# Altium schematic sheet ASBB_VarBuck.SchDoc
size A4
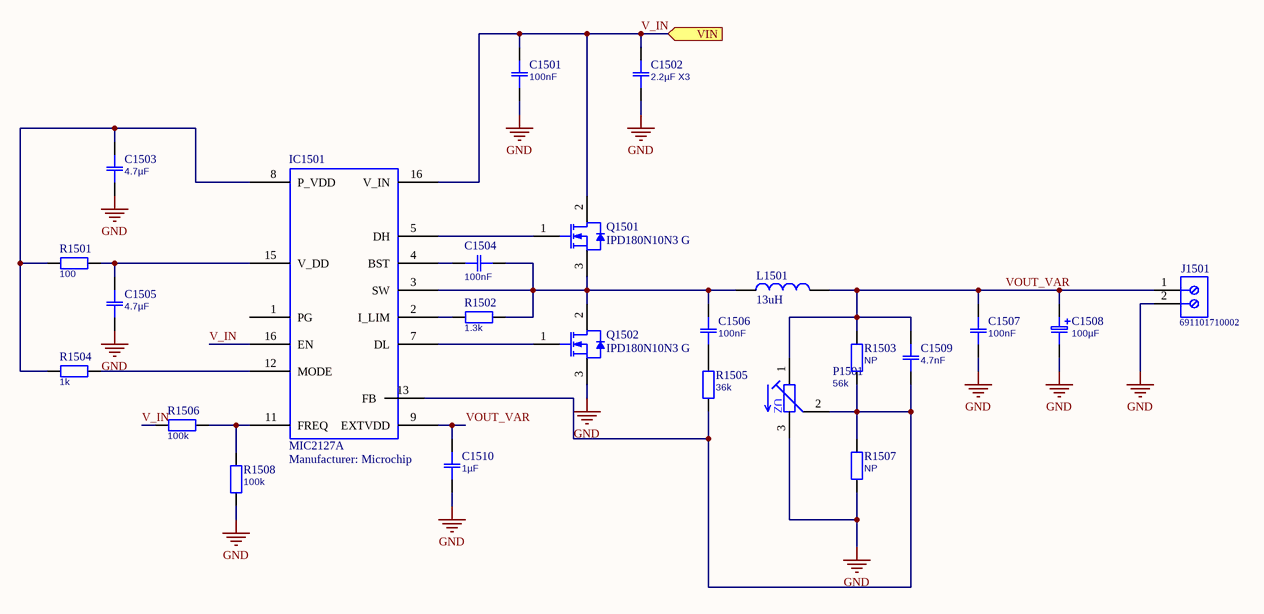
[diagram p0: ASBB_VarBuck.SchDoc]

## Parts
C1501  100nF  [CAP 1206/3216]
C1502  2.2µF X3  [CAP 1206/3216]
C1503  4.7µF  [CAP 1206/3216]
C1504  100nF  [CAP 1206/3216]
C1505  4.7µF  [CAP 1206/3216]
C1506  100nF  [0603]
C1507  100nF  [0603]
C1508  100µF  [CAP ALUM 6.6MM]
C1509  4.7nF  [0603]
C1510  1µF  [0603]
IC1501  MIC2127A  Manufacturer: Microchip  [MCHP-QFN-MG16_N]
J1501  691101710002  [691101710002]
L1501  value 13uH  [WE-HCI_1365_WE-PERM]  (hidden comment: 7443551131)
P1501  56k  [Model 43 Trimmer]
Q1501  IPD180N10N3 G  [INF-PG-TO252-3-11_A_N]
Q1502  IPD180N10N3 G  [INF-PG-TO252-3-11_A_N]
R1501  100  [0603]
R1502  1.3k  [0603]
R1503  NP  [0603]
R1504  1k  [0603]
R1505  36k  [0603]
R1506  100k  [CAP 1206/3216]
R1507  NP  [0603]
R1508  100k  [CAP 1206/3216]

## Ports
VIN (in)

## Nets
GND: C1501.1 C1502.1 C1503.2 C1505.2 C1507.2 C1508.2(-) C1510.2 J1501.2 P1501.3 Q1502.3(SOURCE) R1507.1 R1508.1
V_IN: C1501.2 C1502.2 IC1501.16(EN) Q1501.2(DRAIN) R1506.1 ; port VIN
VOUT_VAR: C1507.1 C1508.1(+) C1509.1 C1510.1 IC1501.9(EXTVDD) J1501.1 L1501.2 P1501.1 R1503.2
NetC1503_1: C1503.1 IC1501.8(P_VDD) R1501.1 R1504.1
NetC1504_1: C1504.1 C1506.1 IC1501.3(SW) L1501.1 Q1501.3(SOURCE) Q1502.2(DRAIN) R1502.2
NetC1504_2: C1504.2 IC1501.4(BST)
NetC1505_1: C1505.1 IC1501.15(V_DD) R1501.2
NetC1506_2: C1506.2 R1505.2
NetC1509_2: C1509.2 IC1501.13(FB) P1501.2 R1503.1 R1505.1 R1507.2
NetIC1501_2: IC1501.2(I_LIM) R1502.1
NetIC1501_5: IC1501.5(DH) Q1501.1(GATE)
NetIC1501_7: IC1501.7(DL) Q1502.1(GATE)
NetIC1501_11: IC1501.11(FREQ) R1506.2 R1508.2
NetIC1501_12: IC1501.12(MODE) R1504.2

Not connected (* = marked no-connect by the designer): IC1501 1(PG)

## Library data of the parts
C1501-C1507 C1509 C1510 = Capacitor
C1508 = Capacitor polarised: Capacitor, polarised
IC1501 = MIC2127A: 75V, Synchronous Buck Controller Featuring ADaptive On-Time Control
J1501 = 691101710002: Series 101 - 5.00 mm Horizontal Entry Modular with Pressure Clamp WR-TBL, 2 pin; Pin Number: 2; Pitch: 5.00 mm
L1501 = 7443551131: WE-HCI SMD Flat Wire High Current Inductor, size 1365, 10A, 13uH; Material: WE-PERM
P1501 = Potentiometer
Q1501 Q1502 = IPD180N10N3 G: N-Channel OptiMOS 3 Power-Transistor, 100 V VDS, 43 A ID, -55 to 175 degC, PG-TO252-3-11, Reel, Green; Manufacturer: Infineon; Green: TRUE; ID (max): 43 A; IDpuls (max): 172 A; Polarity: N; Ptot (max): 71 W; QG: 19 nC; RDS (on) (max): 18 mOhm; Rth: 2.1 K/W; RthJA (max): 75 K/W; VDS (max): 100 V; VGS(th) (max): 3.5 V; VGS(th) (min): 2 V
R1501-R1508 = Resistor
